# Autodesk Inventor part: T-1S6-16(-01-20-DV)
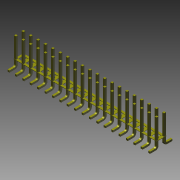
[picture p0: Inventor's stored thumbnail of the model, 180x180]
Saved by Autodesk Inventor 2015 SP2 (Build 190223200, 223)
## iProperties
Category: PARTsolutions
Company: SAMTEC
Created: 2015-08
Part Number: T-1S6-16(-01-20-DV)
Catalog Web Link: www.cadenas.de
Description: TSM Series Terminal-TSM Series - (2,54 mm) .100" Surface Mount Terminal .025" Square Post Header
Vendor: SAMTEC
Document SubType Name: Modeling
Designer: PARTuser1
Manufacturer: SAMTEC
Mass: 0.198411 g
Surface Area: 13.9569 cm^2
Volume: 0.198411 cm^3
Density: 1 g/cm^3
Material: Allgemein
Appearance: PSOLRGB-255-255-0
PSOL_IDENT_0: {$CADENAS_DATA\23d-libs\samtec\modelling\tsm\parts\tsm_terminal.prj},210 {VTYP=3D},{NB=T-1S6-16(-01-
PSOL_IDENT_1: 20-DV)},{LINA=T-1S6-16(-01-20-DV)},{NN=TSM Series Terminal},{DATE=20.05.2015 06:36:02},{GEOMDATE=20.
PSOL_IDENT_2: 05.2015 06:36:00},{VERSION=},{LINEID=10},{LINESUBID=-1},{WBVAR=POS,LS,ROW,POLOPT}  {NB=T-1S6-16(-01-
PSOL_IDENT_3: 20-DV)},{LINA=T-1S6-16(-01-20-DV)},{KT=DUMMY},{PN=T-1S6-16},{POS=20},{LS=-01},{LSALG= '-01','-01','-
PSOL_IDENT_4: 02','-02','-03','-03','-04','-04' ,'-05','-05 (Non-standard option -  Please contact SAMTEC)' },{ROW=
PSOL_IDENT_5: -DV},{ROWALG= '-SV','-SV - Single Vertical', '-SH','-SH - Single Horizontal', '-DV' ,'-DV - Double V
PSOL_IDENT_6: ertical' ,'-DV-S' ,'-DV-S - Double Vertical Molded End Shrouds (Non-standard option -  Please contac
PSOL_IDENT_7: t SAMTEC)', '-DH', '-DH - Double Horizontal' ,  '-MT','-MT - Mixed Technology','-EM','-EM - Edge Mou
PSOL_IDENT_8: nt', '-TM','-TM - Triple Mixed Technology'  },{POLOPT=},{POLOPTALG= '','Not Selected','001','001','0
PSOL_IDENT_9: 02','002','003','003','004','004','005','005','006','006','007','007','008','008','009','009','010','
PSOL_IDENT_10: 010','011','011','012','012','013','013','014','014','015','015','016','016','017','017','018','018'
PSOL_IDENT_11: ,'019','019','020','020','021','021','022','022','023','023','024','024','025','025','026','026','02
PSOL_IDENT_12: 7','027','028','028','029','029','030','030','031','031','032','032','033','033','034','034','035','
PSOL_IDENT_13: 035','036','036','037','037','038','038','039','039','040','040' },{POLOPTMAX=480},{POLOPTMAX2='001'
PSOL_IDENT_14: ,'001','002','002','003','003','004','004','005','005','006','006','007','007','008','008','009','00
PSOL_IDENT_15: 9','010','010','011','011','012','012','013','013','014','014','015','015','016','016','017','017','
PSOL_IDENT_16: 018','018','019','019','020','020','021','021','022','022','023','023','024','024','025','025','026'
PSOL_IDENT_17: ,'026','027','027','028','028','029','029','030','030','031','031','032','032','033','033','034','03
PSOL_IDENT_18: 4','035','035','036','036','037','037','038','038','039','039','040','040'},{POLARIZE='001','001','0
PSOL_IDENT_19: 02','002','003','003','004','004','005','005','006','006','007','007','008','008','009','009','010','
PSOL_IDENT_20: 010','011','011','012','012','013','013','014','014','015','015','016','016','017','017','018','018'
PSOL_IDENT_21: ,'019','019','020','020','021','021','022','022','023','023','024','024','025','025','026','026','02
PSOL_IDENT_22: 7','027','028','028','029','029','030','030','031','031','032','032','033','033','034','034','035','
PSOL_IDENT_23: 035','036','036','037','037','038','038','039','039','040','040','041','041','042','042','043','043'
PSOL_IDENT_24: ,'044','044','045','045','046','046','047','047','048','048','049','049','050','050','051','051','05
PSOL_IDENT_25: 2','052','053','053','054','054','055','055','056','056','057','057','058','058','059','059','060','
PSOL_IDENT_26: 060','061','061','062','062','063','063','064','064','065','065','066','066','067','067','068','068'
PSOL_IDENT_27: ,'069','069','070','070','071','071','072','072','073','073','074','074','075','075','076','076','07
PSOL_IDENT_28: 7','077','078','078','079','079','080','080','081','081','082','082','083','083','084','084','085','
PSOL_IDENT_29: 085','086','086','087','087','088','088','089','089','090','090','091','091','092','092','093','093'
PSOL_IDENT_30: ,'094','094','095','095','096','096','097','097','098','098','099','099','100','100','101','101','10
PSOL_IDENT_31: 2','102','103','103','104','104','105','105','106','106','107','107','108','108','109','109','110','
PSOL_IDENT_32: 110','111','111','112','112','113','113','114','114','115','115','116','116','117','117','118','118'
PSOL_IDENT_33: ,'119','119','120','120','121','121','122','122','123','123','124','124','125','125','126','126','12
PSOL_IDENT_34: 7','127','128','128','129','129','130','130','131','131','132','132','133','133','134','134','135','
PSOL_IDENT_35: 135','136','136','137','137','138','138','139','139','140','140','141','141','142','142','143','143'
PSOL_IDENT_36: ,'144','144','145','145','146','146','147','147','148','148','149','149','150','150'},{POLOPTPN=},{P
PSOL_IDENT_37: OLOPTATOF=0},{BSH=0.230},{CSH=0.180},{BSV=0.230},{DMAXSV=0.208},{AEM=0.230},{POLOE=0},{CDHMT=0.230},
PSOL_IDENT_38: {BDVTM=0.23000},{CDV=0.30300},{POLTM=0}
NN: TSM Series Terminal
NT: TSM Series - (2,54 mm) .100" Surface Mount Terminal .025" Square Post Header
NB: T-1S6-16(-01-20-DV)
NBSYN: $PN.($LS.-$POS.$ROW.$POLOPT.)
LINA: T-1S6-16(-01-20-DV)
POS: 20
LS: -01
ROW: -DV - Double Vertical
POLOPT: Not Selected
SUPPLIER: SAMTEC
ARTICLENO: T-1S6-16(-01-20-DV)
BOMINFO: T-1S6-16(-01-20-DV)
CREATOR: CADENAS GmbH
Title: T-1S6-16(-01-20-DV)
Author: Cadenas PARTsolutions
Comments: TSM Series - (2,54 mm) .100" Surface Mount Terminal .025" Square Post Header
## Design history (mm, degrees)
sketch "Sketch_1"
  geometry: L1 (0.635, 2.578)-(0, 2.578); L2 (0, 2.578)-(0, 0.699); L3 (1.016, -0.318)-(9.652, -0.318); L4 (9.652, -0.318)-(9.652, 0.318); L5 (9.652, 0.318)-(1.143, 0.318); L6 (0.635, 0.826)-(0.635, 2.578); A1 r 1.016 centre (1.016, 0.699) between (0, 0.699) and (1.016, -0.318); A2 r 0.508 centre (1.143, 0.825) between (0.635, 0.826) and (1.143, 0.318)
  constraints: 12 end point, 4 point on circle, 2 centre point
extrude "Extrusion1" join sketch "Sketch_1" stored distance "d0" = 48.895; taper "d1" = 0 deg
sketch "Sketch_4"
  geometry: L1 (-24.498, 2.908)-(-24.498, -0.368); L2 (-24.498, -0.368)-(24.498, -0.368); L3 (24.498, -0.368)-(24.498, 2.908); L4 (24.498, 2.908)-(-24.498, 2.908); L5 (21.958, 2.172)-(21.958, 0.368); L6 (21.958, 0.368)-(23.762, 0.368); L7 (23.762, 0.368)-(23.762, 2.172); L8 (23.762, 2.172)-(21.958, 2.172); L9 (19.418, 2.172)-(19.418, 0.368); L10 (19.418, 0.368)-(21.222, 0.368); L11 (21.222, 0.368)-(21.222, 2.172); L12 (21.222, 2.172)-(19.418, 2.172); L13 (16.878, 2.172)-(16.878, 0.368); L14 (16.878, 0.368)-(18.682, 0.368); L15 (18.682, 0.368)-(18.682, 2.172); L16 (18.682, 2.172)-(16.878, 2.172); L17 (14.338, 2.172)-(14.338, 0.368); L18 (14.338, 0.368)-(16.142, 0.368); L19 (16.142, 0.368)-(16.142, 2.172); L20 (16.142, 2.172)-(14.338, 2.172); L21 (11.798, 2.172)-(11.798, 0.368); L22 (11.798, 0.368)-(13.602, 0.368); L23 (13.602, 0.368)-(13.602, 2.172); L24 (13.602, 2.172)-(11.798, 2.172); L25 (9.258, 2.172)-(9.258, 0.368); L26 (9.258, 0.368)-(11.062, 0.368); L27 (11.062, 0.368)-(11.062, 2.172); L28 (11.062, 2.172)-(9.258, 2.172); L29 (6.718, 2.172)-(6.718, 0.368); L30 (6.718, 0.368)-(8.522, 0.368); L31 (8.522, 0.368)-(8.522, 2.172); L32 (8.522, 2.172)-(6.718, 2.172); L33 (4.178, 2.172)-(4.178, 0.368); L34 (4.178, 0.368)-(5.982, 0.368); L35 (5.982, 0.368)-(5.982, 2.172); L36 (5.982, 2.172)-(4.178, 2.172); L37 (1.638, 2.172)-(1.638, 0.368); L38 (1.638, 0.368)-(3.442, 0.368); L39 (3.442, 0.368)-(3.442, 2.172); L40 (3.442, 2.172)-(1.638, 2.172); L41 (-0.902, 2.172)-(-0.902, 0.368); L42 (-0.902, 0.368)-(0.902, 0.368); L43 (0.902, 0.368)-(0.902, 2.172); L44 (0.902, 2.172)-(-0.902, 2.172); L45 (-3.442, 2.172)-(-3.442, 0.368); L46 (-3.442, 0.368)-(-1.638, 0.368); L47 (-1.638, 0.368)-(-1.638, 2.172); L48 (-1.638, 2.172)-(-3.442, 2.172); L49 (-5.982, 2.172)-(-5.982, 0.368); L50 (-5.982, 0.368)-(-4.178, 0.368); L51 (-4.178, 0.368)-(-4.178, 2.172); L52 (-4.178, 2.172)-(-5.982, 2.172); L53 (-8.522, 2.172)-(-8.522, 0.368); L54 (-8.522, 0.368)-(-6.718, 0.368); L55 (-6.718, 0.368)-(-6.718, 2.172); L56 (-6.718, 2.172)-(-8.522, 2.172); L57 (-11.062, 2.172)-(-11.062, 0.368); L58 (-11.062, 0.368)-(-9.258, 0.368); L59 (-9.258, 0.368)-(-9.258, 2.172); L60 (-9.258, 2.172)-(-11.062, 2.172); L61 (-13.602, 2.172)-(-13.602, 0.368); L62 (-13.602, 0.368)-(-11.798, 0.368); L63 (-11.798, 0.368)-(-11.798, 2.172); L64 (-11.798, 2.172)-(-13.602, 2.172)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
  constraints: 160 end point
extrude "Extrusion2" join sketch "Sketch_4" distance "d2" = 0.127; taper "d3" = 0 deg
sketch "Sketch_5"
  geometry: L1 (0, -3.239)-(0, -5.118); L2 (0, -5.118)-(0.635, -5.118); L3 (0.635, -5.118)-(0.635, -3.365); L4 (1.143, -2.857)-(9.652, -2.857); L5 (9.652, -2.857)-(9.652, -2.223); L6 (9.652, -2.223)-(1.016, -2.223); A1 r 1.016 centre (1.016, -3.239) between (1.016, -2.223) and (0, -3.239); A2 r 0.508 centre (1.143, -3.365) between (1.143, -2.857) and (0.635, -3.365)
  constraints: 12 end point, 4 point on circle, 2 centre point
extrude "Extrusion3" join sketch "Sketch_5" stored distance "d4" = 48.895; taper "d5" = 0 deg
sketch "Sketch_7"
  geometry: L1 (-23.812, 18.059)-(-23.812, 2.667); L2 (-23.812, 2.667)-(-21.907, 2.667); L3 (-21.907, 2.667)-(-21.907, 15.392); L4 (-21.907, 15.392)-(-21.273, 15.392); L5 (-21.273, 15.392)-(-21.273, 2.667); L6 (-21.273, 2.667)-(-19.367, 2.667); L7 (-19.367, 2.667)-(-19.367, 15.392); L8 (-19.367, 15.392)-(-18.733, 15.392); L9 (-18.733, 15.392)-(-18.733, 2.667); L10 (-18.733, 2.667)-(-16.828, 2.667); L11 (-16.828, 2.667)-(-16.828, 15.392); L12 (-16.828, 15.392)-(-16.193, 15.392); L13 (-16.193, 15.392)-(-16.193, 2.667); L14 (-16.193, 2.667)-(-14.287, 2.667); L15 (-14.287, 2.667)-(-14.287, 15.392); L16 (-14.287, 15.392)-(-13.652, 15.392); L17 (-13.652, 15.392)-(-13.652, 2.667); L18 (-13.652, 2.667)-(-11.748, 2.667); L19 (-11.748, 2.667)-(-11.748, 15.392); L20 (-11.748, 15.392)-(-11.113, 15.392); L21 (-11.113, 15.392)-(-11.113, 2.667); L22 (-11.113, 2.667)-(-9.207, 2.667); L23 (-9.207, 2.667)-(-9.207, 15.392); L24 (-9.207, 15.392)-(-8.573, 15.392); L25 (-8.573, 15.392)-(-8.573, 2.667); L26 (-8.573, 2.667)-(-6.668, 2.667); L27 (-6.668, 2.667)-(-6.668, 15.392); L28 (-6.668, 15.392)-(-6.033, 15.392); L29 (-6.033, 15.392)-(-6.033, 2.667); L30 (-6.033, 2.667)-(-4.128, 2.667); L31 (-4.128, 2.667)-(-4.128, 15.392); L32 (-4.128, 15.392)-(-3.493, 15.392); L33 (-3.493, 15.392)-(-3.493, 2.667); L34 (-3.493, 2.667)-(-1.587, 2.667); L35 (-1.587, 2.667)-(-1.587, 15.392); L36 (-1.587, 15.392)-(-0.953, 15.392); L37 (-0.953, 15.392)-(-0.953, 2.667); L38 (-0.953, 2.667)-(0.953, 2.667); L39 (0.953, 2.667)-(0.953, 15.392); L40 (0.953, 15.392)-(1.587, 15.392); L41 (1.587, 15.392)-(1.587, 2.667); L42 (1.587, 2.667)-(3.493, 2.667); L43 (3.493, 2.667)-(3.493, 15.392); L44 (3.493, 15.392)-(4.128, 15.392); L45 (4.128, 15.392)-(4.128, 2.667); L46 (4.128, 2.667)-(6.033, 2.667); L47 (6.033, 2.667)-(6.033, 15.392); L48 (6.033, 15.392)-(6.668, 15.392); L49 (6.668, 15.392)-(6.668, 2.667); L50 (6.668, 2.667)-(8.573, 2.667); L51 (8.573, 2.667)-(8.573, 15.392); L52 (8.573, 15.392)-(9.207, 15.392); L53 (9.207, 15.392)-(9.207, 2.667); L54 (9.207, 2.667)-(11.113, 2.667); L55 (11.113, 2.667)-(11.113, 15.392); L56 (11.113, 15.392)-(11.748, 15.392); L57 (11.748, 15.392)-(11.748, 2.667); L58 (11.748, 2.667)-(13.652, 2.667); L59 (13.652, 2.667)-(13.652, 15.392); L60 (13.652, 15.392)-(14.287, 15.392); L61 (14.287, 15.392)-(14.287, 2.667); L62 (14.287, 2.667)-(16.193, 2.667); L63 (16.193, 2.667)-(16.193, 15.392); L64 (16.193, 15.392)-(16.828, 15.392)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
  constraints: 152 end point
extrude "Extrusion4" cut sketch "Sketch_7" stored distance "d6" = 10.16; taper "d7" = 0 deg
sketch "Sketch_8"
  geometry: L1 (-23.812, -12.852)-(23.812, -12.852); L2 (23.812, -12.852)-(23.812, 2.54); L3 (23.812, 2.54)-(21.907, 2.54); L4 (21.907, 2.54)-(21.907, -12.598); L5 (21.907, -12.598)-(21.273, -12.598); L6 (21.273, -12.598)-(21.273, 2.54); L7 (21.273, 2.54)-(19.367, 2.54); L8 (19.367, 2.54)-(19.367, -12.598); L9 (19.367, -12.598)-(18.733, -12.598); L10 (18.733, -12.598)-(18.733, 2.54); L11 (18.733, 2.54)-(16.828, 2.54); L12 (16.828, 2.54)-(16.828, -12.598); L13 (16.828, -12.598)-(16.193, -12.598); L14 (16.193, -12.598)-(16.193, 2.54); L15 (16.193, 2.54)-(14.287, 2.54); L16 (14.287, 2.54)-(14.287, -12.598); L17 (14.287, -12.598)-(13.652, -12.598); L18 (13.652, -12.598)-(13.652, 2.54); L19 (13.652, 2.54)-(11.748, 2.54); L20 (11.748, 2.54)-(11.748, -12.598); L21 (11.748, -12.598)-(11.113, -12.598); L22 (11.113, -12.598)-(11.113, 2.54); L23 (11.113, 2.54)-(9.207, 2.54); L24 (9.207, 2.54)-(9.207, -12.598); L25 (9.207, -12.598)-(8.573, -12.598); L26 (8.573, -12.598)-(8.573, 2.54); L27 (8.573, 2.54)-(6.668, 2.54); L28 (6.668, 2.54)-(6.668, -12.598); L29 (6.668, -12.598)-(6.033, -12.598); L30 (6.033, -12.598)-(6.033, 2.54); L31 (6.033, 2.54)-(4.128, 2.54); L32 (4.128, 2.54)-(4.128, -12.598); L33 (4.128, -12.598)-(3.493, -12.598); L34 (3.493, -12.598)-(3.493, 2.54); L35 (3.493, 2.54)-(1.587, 2.54); L36 (1.587, 2.54)-(1.587, -12.598); L37 (1.587, -12.598)-(0.953, -12.598); L38 (0.953, -12.598)-(0.953, 2.54); L39 (0.953, 2.54)-(-0.953, 2.54); L40 (-0.953, 2.54)-(-0.953, -12.598); L41 (-0.953, -12.598)-(-1.587, -12.598); L42 (-1.587, -12.598)-(-1.587, 2.54); L43 (-1.587, 2.54)-(-3.493, 2.54); L44 (-3.493, 2.54)-(-3.493, -12.598); L45 (-3.493, -12.598)-(-4.128, -12.598); L46 (-4.128, -12.598)-(-4.128, 2.54); L47 (-4.128, 2.54)-(-6.033, 2.54); L48 (-6.033, 2.54)-(-6.033, -12.598); L49 (-6.033, -12.598)-(-6.668, -12.598); L50 (-6.668, -12.598)-(-6.668, 2.54); L51 (-6.668, 2.54)-(-8.573, 2.54); L52 (-8.573, 2.54)-(-8.573, -12.598); L53 (-8.573, -12.598)-(-9.207, -12.598); L54 (-9.207, -12.598)-(-9.207, 2.54); L55 (-9.207, 2.54)-(-11.113, 2.54); L56 (-11.113, 2.54)-(-11.113, -12.598); L57 (-11.113, -12.598)-(-11.748, -12.598); L58 (-11.748, -12.598)-(-11.748, 2.54); L59 (-11.748, 2.54)-(-13.652, 2.54); L60 (-13.652, 2.54)-(-13.652, -12.598); L61 (-13.652, -12.598)-(-14.287, -12.598); L62 (-14.287, -12.598)-(-14.287, 2.54); L63 (-14.287, 2.54)-(-16.193, 2.54); L64 (-16.193, 2.54)-(-16.193, -12.598)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
  constraints: 152 end point
extrude "Extrusion5" cut sketch "Sketch_8" stored distance "d8" = 15.24; taper "d9" = 0 deg
node "terminal_dv_XY"
node "terminal_dv_YZ"
node "terminal_dv_ZX"
node "terminal_dv_X"
node "terminal_dv_Y"
node "terminal_dv_Z"
node "terminal_dv_Center"
body "Solid1"
